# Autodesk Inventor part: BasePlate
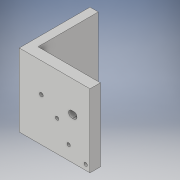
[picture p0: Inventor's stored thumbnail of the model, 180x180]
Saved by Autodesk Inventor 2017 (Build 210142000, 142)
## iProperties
Created: 2017-04
Part Number: BasePlate
Material: Generic
Document SubType Name: Modeling
Designer: 1460374
Density: 1 g/cm^3
Appearance: Default
Author: 1460374
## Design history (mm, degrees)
sketch "Sketch1"
  geometry: L1 (70, 60)-(-70, 60); L2 (-70, 60)-(-70, -60); L3 (-70, -60)-(70, -60); L4 (70, -60)-(70, 60); L5 (70, 60)-(-70, -60); L6 (-70, 60)-(70, -60); 2 further points
  constraints: 12 end point, 2 midpoint, 2 parallel, 1 coincident, 1 horizontal, 1 perpendicular
  dimensions: "d0" = 140 distance of L3.end L2.end; "d1" = 120 distance of L2.end L1.end
extrude "Extrusion1" new body sketch "Sketch1" distance "d2" = 16; taper "d3" = 0 deg
sketch "Sketch2"
  geometry: L1 (-60, 70)-(-60, -70) reference; L2 (-60, -70)-(-76, -70); L3 (-76, -70)-(-76, 70); L4 (-76, 70)-(-60, 70); L5 (-60, 70)-(-60, -70); 1 further point
  constraints: 8 end point, 2 parallel, 1 horizontal, 1 perpendicular
  dimensions: "d4" = 16 distance of L3.end L4.end
extrude "Extrusion2" join sketch "Sketch2" stored distance "d5" = 20; taper "d6" = 0 deg
sketch "Sketch3"
  geometry: L1 (60, -70)-(-76, -70) reference; L2 (60, 70)-(-76, 70) reference; L3 (-76, -70)-(-56, -70); L4 (-56, -70)-(-56, 70); L5 (-56, 70)-(-76, 70); L6 (-76, 70)-(-76, -70); 1 further point
  constraints: 8 end point, 2 parallel, 1 horizontal, 1 perpendicular, 1 point on line
  dimensions: "d7" = 20 distance of L5.end L4.end
extrude "Extrusion3" join sketch "Sketch3" distance "d8" = 120; taper "d9" = 0 deg
sketch "Sketch5"
  geometry: C1 r 3.225 at (-111.686, 10.128) reference; C2 r 3.225 at (-78.937, 26.503) reference; C3 r 3.225 at (-56.718, 59.374) reference; 1 further point
extrude "Extrusion5" cut sketch "Sketch5" stored distance "d12" = 25.4; taper "d13" = 0 deg
sketch "Sketch7"
  geometry: L1 (45.805, 83.881)-(43.956, 83.936) reference; L2 (43.956, 83.936)-(43.927, 82.937) reference; L3 (43.927, 82.937)-(45.775, 82.882) reference; C1 r 3.386 at (42.442, 83.481); C2 r 3.586 at (42.442, 83.481); A1 r 3.386 centre (42.442, 83.481) between (45.775, 82.882) and (45.805, 83.881) reference; A2 r 3.386 centre (42.442, 83.481) between (45.805, 83.881) and (45.775, 82.882) reference; A3 r 3.586 centre (42.442, 83.481) between (45.972, 82.847) and (46.003, 83.905); A4 r 3.586 centre (42.442, 83.481) between (46.003, 83.905) and (45.972, 82.847); 1 further point
  constraints: 8 point on circle, 6 centre point, 6 end point, 2 coincident, 2 concentric, 11 other
  dimensions: "d17" = 0.2 radial gap between concentric circles of A1 A3; "d18" = 0.2 radial gap between concentric circles of A2 A4
extrude "Extrusion7" cut sketch "Sketch7" stored distance "d19" = 25.4; taper "d20" = 0 deg
sketch "Sketch9"
  geometry: L1 (-85.079, 71.815)-(-102.079, 71.815) reference; L2 (-85.079, 88.815)-(-85.079, 71.815) reference; L3 (-102.079, 88.815)-(-85.079, 88.815) reference; L4 (-102.079, 71.815)-(-102.079, 88.815) reference; L5 (-85.079, 80.315)-(-91.429, 80.315); L6 (-85.079, 80.315)-(-78.729, 80.315); L7 (-85.079, 80.315)-(-78.729, 80.315); A1 r 6.35 centre (-85.079, 80.315) between (-86.898, 74.231) and (-86.898, 86.399); A2 r 6.35 centre (-88.718, 80.315) between (-86.898, 86.399) and (-86.898, 74.231); 1 further point
  constraints: 6 end point, 4 point on circle, 3 horizontal, 2 centre point, 1 coincident, 1 collinear, 1 midpoint
  dimensions: "d21" = 6.35 distance of L5.start L5.end; "d22" = 6.35 distance of L5.start L6.end; "d23" = 0 distance between parallel lines of L6 L7 (derived)
extrude "Extrusion8" cut sketch "Sketch9" distance "d24" = 20.6375; taper "d25" = 0 deg
body "Solid1"
node "Reference10"
node "Reference11"
node "Reference12"
node "Reference14"
node "Reference15"
node "Reference16"
node "Reference17"
